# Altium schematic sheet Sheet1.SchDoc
size A4
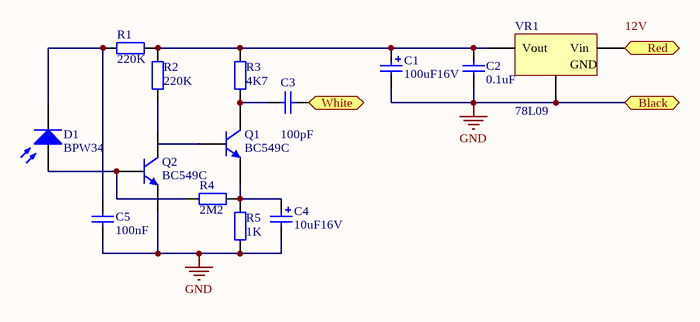
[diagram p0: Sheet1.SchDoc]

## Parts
C1  value 100uF16V  [POLAR0.8]  (hidden comment: Cap Pol2)
C2  value 0.1uF  [RAD-0.3]  (hidden comment: Cap)
C3  value 100pF  [RAD-0.3]  (hidden comment: Cap)
C4  value 10uF16V  [POLAR0.8]  (hidden comment: Cap Pol2)
C5  value 100nF  [RAD-0.3]  (hidden comment: Cap)
D1  BPW34  [PIN2]
Q1  BC549C  [TO-226-AA]
Q2  BC549C  [TO-226-AA]
R1  value 220K  [AXIAL-0.4]  (hidden comment: Res2)
R2  value 220K  [AXIAL-0.4]  (hidden comment: Res2)
R3  value 4K7  [AXIAL-0.4]  (hidden comment: Res2)
R4  value 2M2  [AXIAL-0.4]  (hidden comment: Res2)
R5  value 1K  [AXIAL-0.4]  (hidden comment: Res2)
VR1  78L09  [D2PAK_N]

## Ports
Black, Red, White

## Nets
GND: C1.2 C2.1 C4.2 C5.1 Q2.3(E) R5.1 VR1.2(GND) ; port Black
Red: VR1.1(Vin) ; port Red
White: C3.2 ; port White
NetC1_1: C1.1 C2.2 R1.1 R2.2 R3.2 VR1.3(Vout)
NetC3_1: C3.1 Q1.1(C) R3.1
NetC4_1: C4.1 Q1.3(E) R4.1 R5.2
NetC5_2: C5.2 D1.2(K) R1.2
NetD1_1: D1.1(A) Q2.2(B) R4.2
NetQ2_1: Q2.1(C) R2.1

Not connected (* = marked no-connect by the designer): Q1 2(B)

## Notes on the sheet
- Labels drawn without touching a wire or pin: 12V

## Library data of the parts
C1 C4 = Cap Pol2: Polarized Capacitor (Axial)
C2 C3 C5 = Cap: Capacitor
D1 = Photo Sen: Photosensitive Diode
Q1 Q2 = NPN: NPN Bipolar Transistor
R1-R5 = Res2: Resistor
VR1 = Volt Reg: Voltage Regulator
